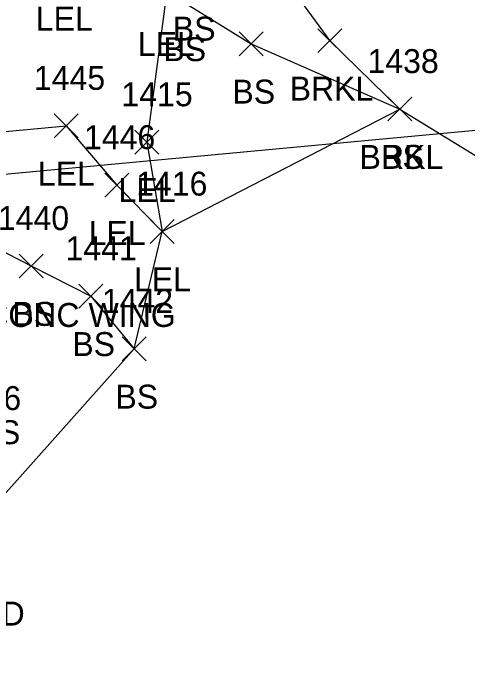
# Model space of a CAD drawing. Extents: x 1505684 to 1510253, y 730355 to 731397.
# Drawn here: x 1510103.6 to 1510141.5, y 730850.1 to 730905.9 of the extents above; entities that cross this region are included whole.
import ezdxf

# ---------------------------------------------------------------- set-up
doc = ezdxf.new("R2010")
doc.units = 0
for name, color, linetype in [('BELB', 7, 'Continuous'), ('C_C', 7, 'Continuous'), ('L_A', 7, 'Continuous'), ('L_I', 7, 'Continuous'), ('L_TIC', 7, 'Continuous'), ('LARO', 7, 'Continuous'), ('LAWE', 7, 'Continuous'), ('LELB', 7, 'Continuous'), ('LSOGP', 7, 'Continuous')]:
    doc.layers.add(name, color=color, linetype=linetype)

msp = doc.modelspace()

# ---------------------------------------------------------------- linework, layer by layer
at = {"layer": 'BELB'}
msp.add_lwpolyline([(1510099.175, 730891.61), (1510099.525, 730892.156), (1510145.724, 730896.473), (1510191.184, 730900.384), (1510192.217, 730899.998), (1510192.409, 730899.895)], dxfattribs=at)
at = {"layer": 'L_TIC'}
for points in [[(1510128.977, 730902.6), (1510130.977, 730904.6)], [(1510130.977, 730902.6), (1510128.977, 730904.6)], [(1510122.406, 730902.345), (1510124.406, 730904.345)], [(1510124.406, 730902.345), (1510122.406, 730904.345)], [(1510134.81, 730896.892), (1510136.81, 730898.892)], [(1510136.81, 730896.892), (1510134.81, 730898.892)], [(1510134.81, 730896.892), (1510136.81, 730898.892)], [(1510136.81, 730896.892), (1510134.81, 730898.892)], [(1510106.98, 730895.493), (1510108.98, 730897.493)], [(1510108.98, 730895.493), (1510106.98, 730897.493)], [(1510113.713, 730894.122), (1510115.713, 730896.122)], [(1510115.713, 730894.122), (1510113.713, 730896.122)], [(1510111.214, 730890.537), (1510113.214, 730892.537)], [(1510113.214, 730890.537), (1510111.214, 730892.537)], [(1510114.997, 730886.658), (1510116.997, 730888.658)], [(1510116.997, 730886.658), (1510114.997, 730888.658)], [(1510104.059, 730883.781), (1510106.059, 730885.781)], [(1510106.059, 730883.781), (1510104.059, 730885.781)], [(1510109.05, 730881.256), (1510111.05, 730883.256)], [(1510111.05, 730881.256), (1510109.05, 730883.256)], [(1510112.646, 730876.864), (1510114.646, 730878.864)], [(1510114.646, 730876.864), (1510112.646, 730878.864)]]:
    msp.add_lwpolyline(points, dxfattribs=at)
at = {"layer": 'LARO'}
for points in [[(1510101.917, 730994.212), (1510104.828, 730981.217), (1510106.455, 730957.263), (1510106.967, 730955.278), (1510106.13, 730950.829), (1510106.501, 730944.322), (1510107.441, 730934.545), (1510104.318, 730922.85), (1510106.817, 730918.239), (1510107.804, 730909.428), (1510116.32, 730907.332), (1510114.713, 730895.122), (1510115.997, 730887.658)], [(1510099.881, 730895.726), (1510107.98, 730896.493), (1510112.214, 730891.537)], [(1510112.214, 730891.537), (1510115.997, 730887.658)]]:
    msp.add_lwpolyline(points, dxfattribs=at)
at = {"layer": 'LAWE'}
msp.add_lwpolyline([(1510122.024, 730991.611), (1510124.894, 730974.664), (1510119.393, 730963.807), (1510121.985, 730952.758), (1510123.743, 730944.672), (1510127.824, 730935.898), (1510125.591, 730932.689), (1510122.326, 730914.067), (1510129.977, 730903.6), (1510135.81, 730897.892)], dxfattribs=at)
at = {"layer": 'LELB'}
for points in [[(1510106.378, 730998.053), (1510106.935, 730982.19), (1510109.019, 730972.094), (1510109.107, 730961.84), (1510106.967, 730955.278), (1510109.675, 730944.384), (1510110.308, 730935.125), (1510114.076, 730923.399), (1510118.436, 730908.609), (1510114.191, 730912.258), (1510117.647, 730906.891), (1510123.406, 730903.345), (1510135.81, 730897.892)], [(1510097.956, 730888.448), (1510105.059, 730884.781), (1510110.05, 730882.256), (1510113.646, 730877.864)]]:
    msp.add_lwpolyline(points, dxfattribs=at)
at = {"layer": 'LSOGP'}
msp.add_lwpolyline([(1510034.056, 730907.411), (1510037.72, 730889.421), (1510042.84, 730876.206), (1510041.612, 730870.022), (1510044.642, 730859.104), (1510052.661, 730850.144), (1510065.293, 730854.837), (1510075.69, 730858.322), (1510079.252, 730859.702), (1510086.745, 730861.156), (1510092.094, 730858.471), (1510097.506, 730859.747), (1510113.646, 730877.864), (1510115.997, 730887.658), (1510135.81, 730897.892), (1510165.212, 730879.843)], dxfattribs=at)

# ---------------------------------------------------------------- texts
at = {"layer": 'C_C'}
for s, p in [('BM6=CHSQ TOP SW CONC WING', (1510074.404, 730879.688)), ('IP G.DUBOIS', (1510087.809, 730869.895))]:
    msp.add_text(s, height=2, dxfattribs=at).set_placement(p)
at = {"layer": 'L_A'}
for s, p in [('LEL', (1510105.442, 730904.428)), ('BS', (1510116.877, 730903.609)), ('LEL', (1510113.957, 730902.332)), ('BS', (1510116.088, 730901.891)), ('BRKL', (1510126.623, 730898.6)), ('BS', (1510121.847, 730898.345)), ('BRKL', (1510132.456, 730892.892)), ('BS', (1510134.251, 730892.892)), ('LEL', (1510105.618, 730891.493)), ('LEL', (1510112.351, 730890.122)), ('LEL', (1510109.852, 730886.537)), ('LEL', (1510113.635, 730882.658)), ('BS', (1510103.5, 730879.781)), ('BS', (1510108.491, 730877.256)), ('BS', (1510112.087, 730872.864)), ('CONCPAD', (1510091.152, 730854.747))]:
    msp.add_text(s, height=2, dxfattribs=at).set_placement(p)
at = {"layer": 'L_I'}
for s, p in [('1438', (1510133.117, 730900.892)), ('1438', (1510133.117, 730900.892)), ('1445', (1510105.287, 730899.493)), ('1415', (1510112.587, 730898.122)), ('1446', (1510109.466, 730894.537)), ('1416', (1510113.816, 730890.658)), ('1440', (1510102.279, 730887.781)), ('1441', (1510107.924, 730885.256)), ('1442', (1510110.953, 730880.864)), ('1156', (1510098.28, 730872.744))]:
    msp.add_text(s, height=2, dxfattribs=at).set_placement(p)

doc.saveas('drawing.dxf')
